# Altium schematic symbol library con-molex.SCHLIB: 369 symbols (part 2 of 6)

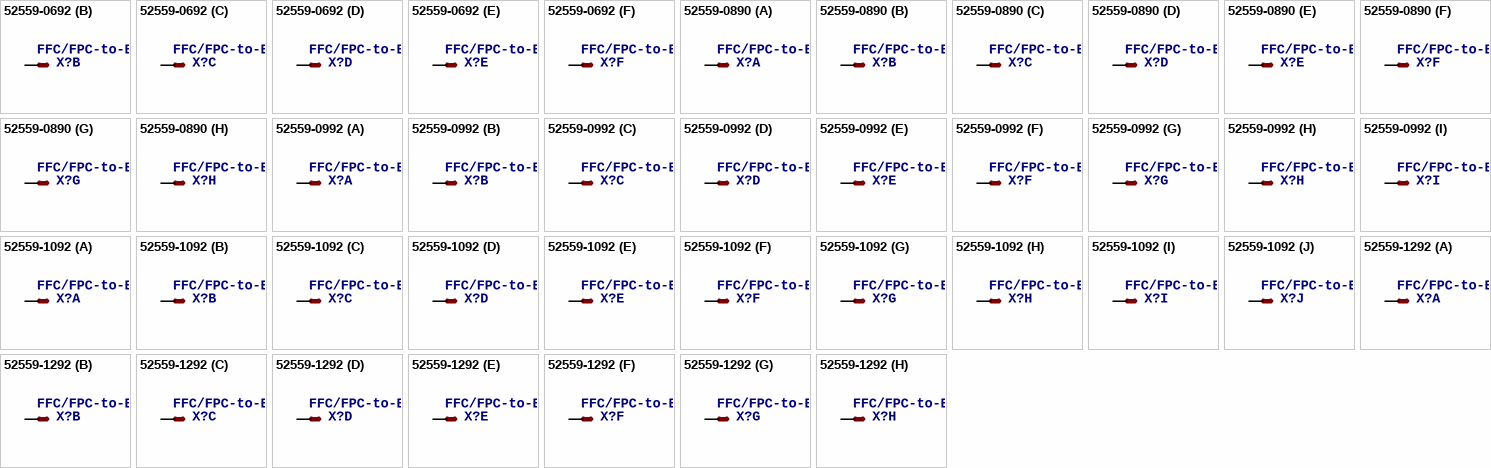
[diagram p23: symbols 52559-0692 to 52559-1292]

## 52559-0692
designator X?, comment FFC/FPC-to-Board  0.50mm (.020") SMT, Vertical, ZIF Receptacle   Source: http://www.molex.com/product/ffc/52559.html
MPN: 52559-0692
footprint 52559-0692
part A pins: 1 S
part B pins: 2 S
part C pins: 3 S
part D pins: 4 S
part E pins: 5 S
part F pins: 6 S

## 52559-0890
designator X?, comment FFC/FPC-to-Board  0.50mm (.020") SMT, Vertical, ZIF Receptacle   Source: http://www.molex.com/product/ffc/52559.html
footprint 52559-0890
part A pins: 1 S
part B pins: 2 S
part C pins: 3 S
part D pins: 4 S
part E pins: 5 S
part F pins: 6 S
part G pins: 7 S
part H pins: 8 S

## 52559-0992
designator X?, comment FFC/FPC-to-Board  0.50mm (.020") SMT, Vertical, ZIF Receptacle   Source: http://www.molex.com/product/ffc/52559.html
footprint 52559-0992
part A pins: 1 S
part B pins: 2 S
part C pins: 3 S
part D pins: 4 S
part E pins: 5 S
part F pins: 6 S
part G pins: 7 S
part H pins: 8 S
part I pins: 9 S

## 52559-1092
designator X?, comment FFC/FPC-to-Board  0.50mm (.020") SMT, Vertical, ZIF Receptacle   Source: http://www.molex.com/product/ffc/52559.html
MPN: 52559-1092
footprint 52559-1092
part A pins: 1 S
part B pins: 2 S
part C pins: 3 S
part D pins: 4 S
part E pins: 5 S
part F pins: 6 S
part G pins: 7 S
part H pins: 8 S
part I pins: 9 S
part J pins: 10 S

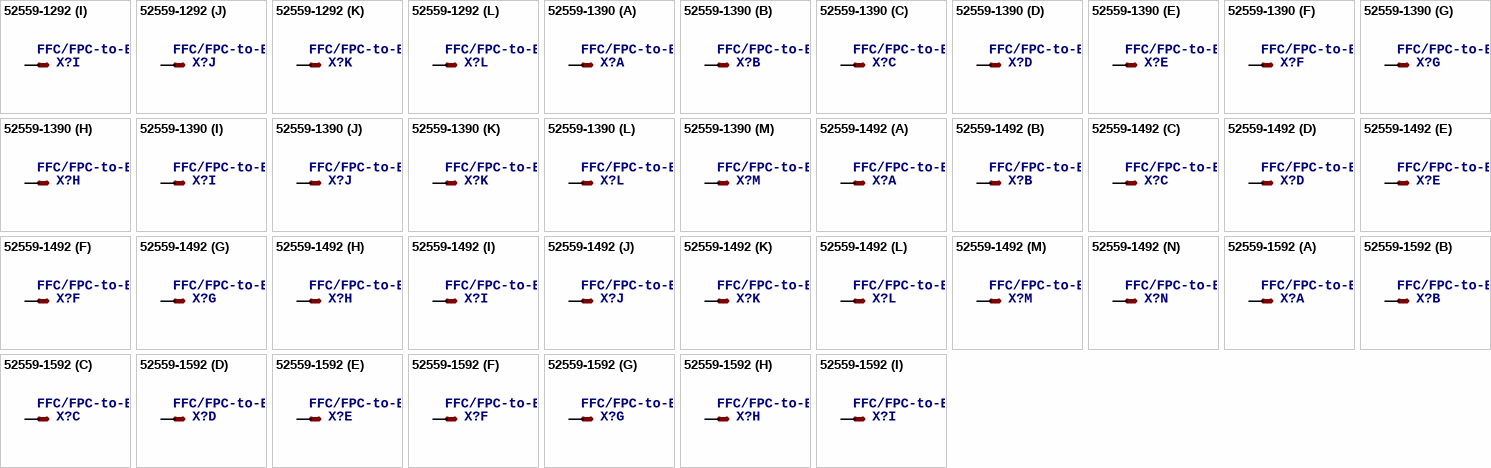
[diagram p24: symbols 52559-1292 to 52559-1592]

## 52559-1292
designator X?, comment FFC/FPC-to-Board  0.50mm (.020") SMT, Vertical, ZIF Receptacle   Source: http://www.molex.com/product/ffc/52559.html
MPN: 52559-1292
footprint 52559-1292
part A pins: 1 S
part B pins: 2 S
part C pins: 3 S
part D pins: 4 S
part E pins: 5 S
part F pins: 6 S
part G pins: 7 S
part H pins: 8 S
part I pins: 9 S
part J pins: 10 S
part K pins: 11 S
part L pins: 12 S

## 52559-1390
designator X?, comment FFC/FPC-to-Board  0.50mm (.020") SMT, Vertical, ZIF Receptacle   Source: http://www.molex.com/product/ffc/52559.html
MPN: 52559-1390
footprint 52559-1390
part A pins: 1 S
part B pins: 2 S
part C pins: 3 S
part D pins: 4 S
part E pins: 5 S
part F pins: 6 S
part G pins: 7 S
part H pins: 8 S
part I pins: 9 S
part J pins: 10 S
part K pins: 11 S
part L pins: 12 S
part M pins: 13 S

## 52559-1492
designator X?, comment FFC/FPC-to-Board  0.50mm (.020") SMT, Vertical, ZIF Receptacle   Source: http://www.molex.com/product/ffc/52559.html
MPN: 52559-1492
footprint 52559-1492
part A pins: 1 S
part B pins: 2 S
part C pins: 3 S
part D pins: 4 S
part E pins: 5 S
part F pins: 6 S
part G pins: 7 S
part H pins: 8 S
part I pins: 9 S
part J pins: 10 S
part K pins: 11 S
part L pins: 12 S
part M pins: 13 S
part N pins: 14 S

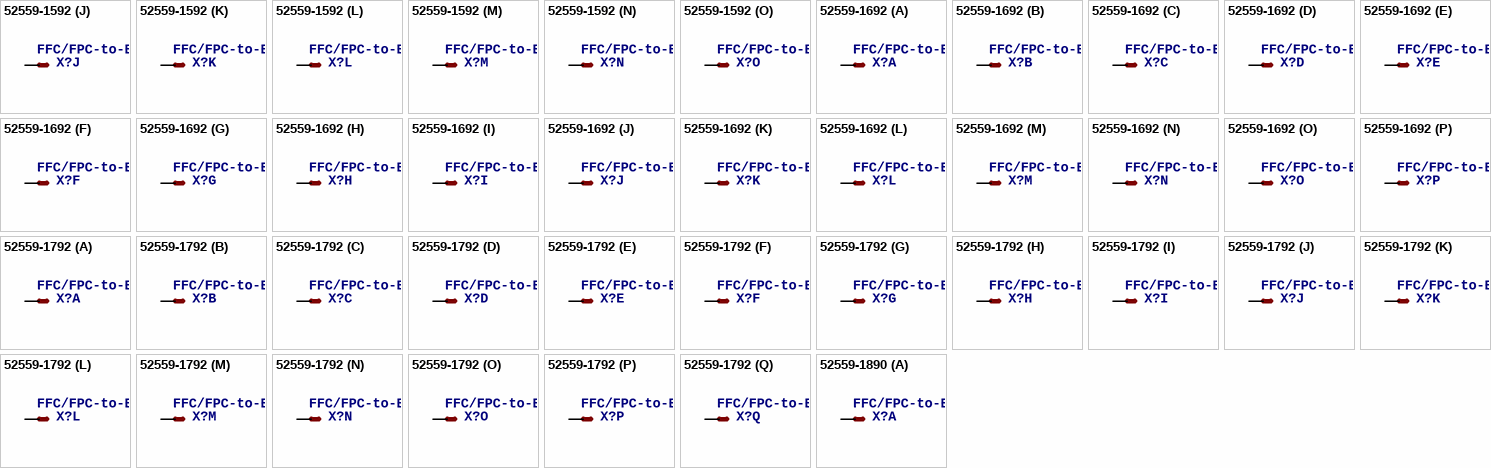
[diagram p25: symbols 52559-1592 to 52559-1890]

## 52559-1592
designator X?, comment FFC/FPC-to-Board  0.50mm (.020") SMT, Vertical, ZIF Receptacle   Source: http://www.molex.com/product/ffc/52559.html
footprint 52559-1592
part A pins: 1 S
part B pins: 2 S
part C pins: 3 S
part D pins: 4 S
part E pins: 5 S
part F pins: 6 S
part G pins: 7 S
part H pins: 8 S
part I pins: 9 S
part J pins: 10 S
part K pins: 11 S
part L pins: 12 S
part M pins: 13 S
part N pins: 14 S
part O pins: 15 S

## 52559-1692
designator X?, comment FFC/FPC-to-Board  0.50mm (.020") SMT, Vertical, ZIF Receptacle   Source: http://www.molex.com/product/ffc/52559.html
footprint 52559-1692
part A pins: 1 S
part B pins: 2 S
part C pins: 3 S
part D pins: 4 S
part E pins: 5 S
part F pins: 6 S
part G pins: 7 S
part H pins: 8 S
part I pins: 9 S
part J pins: 10 S
part K pins: 11 S
part L pins: 12 S
part M pins: 13 S
part N pins: 14 S
part O pins: 15 S
part P pins: 16 S

## 52559-1792
designator X?, comment FFC/FPC-to-Board  0.50mm (.020") SMT, Vertical, ZIF Receptacle   Source: http://www.molex.com/product/ffc/52559.html
footprint 52559-1792
part A pins: 1 S
part B pins: 2 S
part C pins: 3 S
part D pins: 4 S
part E pins: 5 S
part F pins: 6 S
part G pins: 7 S
part H pins: 8 S
part I pins: 9 S
part J pins: 10 S
part K pins: 11 S
part L pins: 12 S
part M pins: 13 S
part N pins: 14 S
part O pins: 15 S
part P pins: 16 S
part Q pins: 17 S

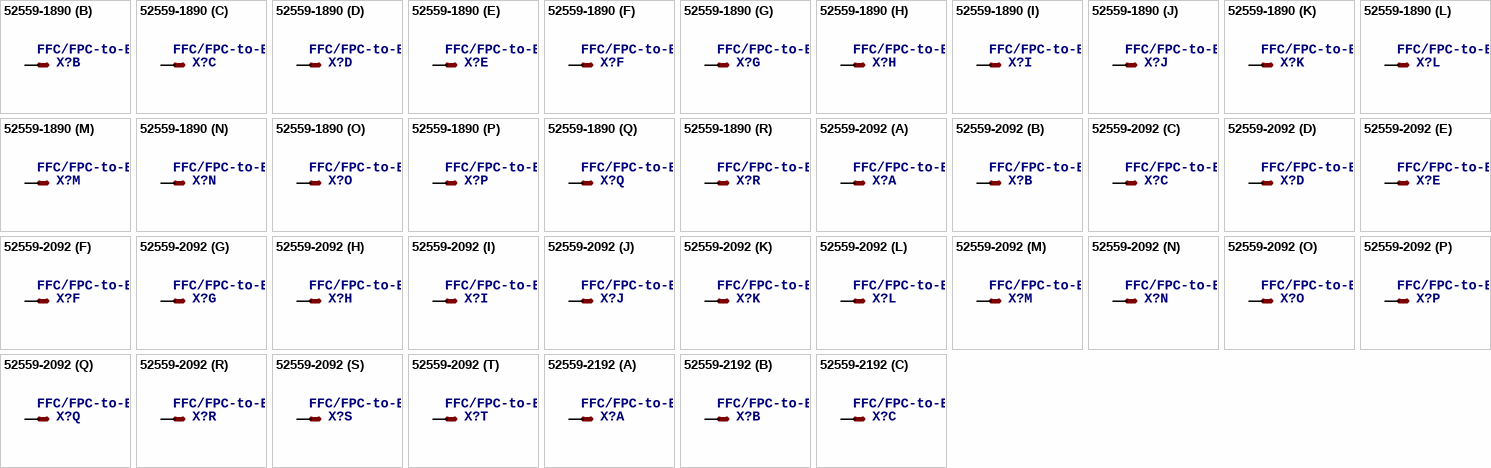
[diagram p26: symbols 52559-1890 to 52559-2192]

## 52559-1890
designator X?, comment FFC/FPC-to-Board  0.50mm (.020") SMT, Vertical, ZIF Receptacle   Source: http://www.molex.com/product/ffc/52559.html
MPN: 52559-1890
footprint 52559-1890
part A pins: 1 S
part B pins: 2 S
part C pins: 3 S
part D pins: 4 S
part E pins: 5 S
part F pins: 6 S
part G pins: 7 S
part H pins: 8 S
part I pins: 9 S
part J pins: 10 S
part K pins: 11 S
part L pins: 12 S
part M pins: 13 S
part N pins: 14 S
part O pins: 15 S
part P pins: 16 S
part Q pins: 17 S
part R pins: 18 S

## 52559-2092
designator X?, comment FFC/FPC-to-Board  0.50mm (.020") SMT, Vertical, ZIF Receptacle   Source: http://www.molex.com/product/ffc/52559.html
footprint 52559-2092
part A pins: 1 S
part B pins: 2 S
part C pins: 3 S
part D pins: 4 S
part E pins: 5 S
part F pins: 6 S
part G pins: 7 S
part H pins: 8 S
part I pins: 9 S
part J pins: 10 S
part K pins: 11 S
part L pins: 12 S
part M pins: 13 S
part N pins: 14 S
part O pins: 15 S
part P pins: 16 S
part Q pins: 17 S
part R pins: 18 S
part S pins: 19 S
part T pins: 20 S

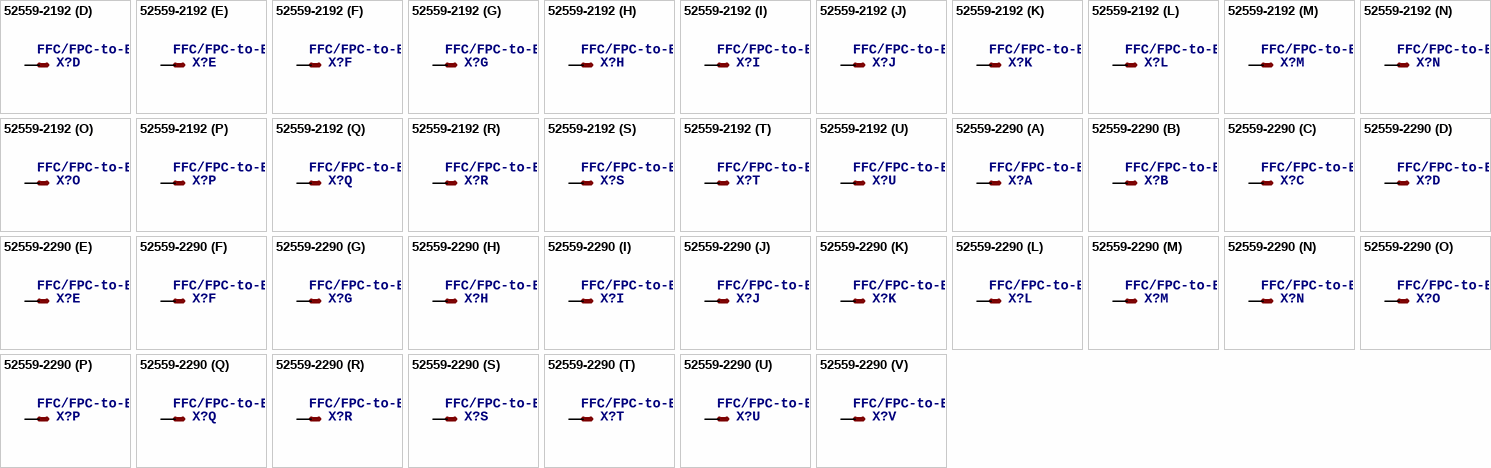
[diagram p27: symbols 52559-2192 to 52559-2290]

## 52559-2192
designator X?, comment FFC/FPC-to-Board  0.50mm (.020") SMT, Vertical, ZIF Receptacle   Source: http://www.molex.com/product/ffc/52559.html
footprint 52559-2192
part A pins: 1 S
part B pins: 2 S
part C pins: 3 S
part D pins: 4 S
part E pins: 5 S
part F pins: 6 S
part G pins: 7 S
part H pins: 8 S
part I pins: 9 S
part J pins: 10 S
part K pins: 11 S
part L pins: 12 S
part M pins: 13 S
part N pins: 14 S
part O pins: 15 S
part P pins: 16 S
part Q pins: 17 S
part R pins: 18 S
part S pins: 19 S
part T pins: 20 S
part U pins: 21 S

## 52559-2290
designator X?, comment FFC/FPC-to-Board  0.50mm (.020") SMT, Vertical, ZIF Receptacle   Source: http://www.molex.com/product/ffc/52559.html
MPN: 52559-2290
footprint 52559-2290
part A pins: 1 S
part B pins: 2 S
part C pins: 3 S
part D pins: 4 S
part E pins: 5 S
part F pins: 6 S
part G pins: 7 S
part H pins: 8 S
part I pins: 9 S
part J pins: 10 S
part K pins: 11 S
part L pins: 12 S
part M pins: 13 S
part N pins: 14 S
part O pins: 15 S
part P pins: 16 S
part Q pins: 17 S
part R pins: 18 S
part S pins: 19 S
part T pins: 20 S
part U pins: 21 S
part V pins: 22 S

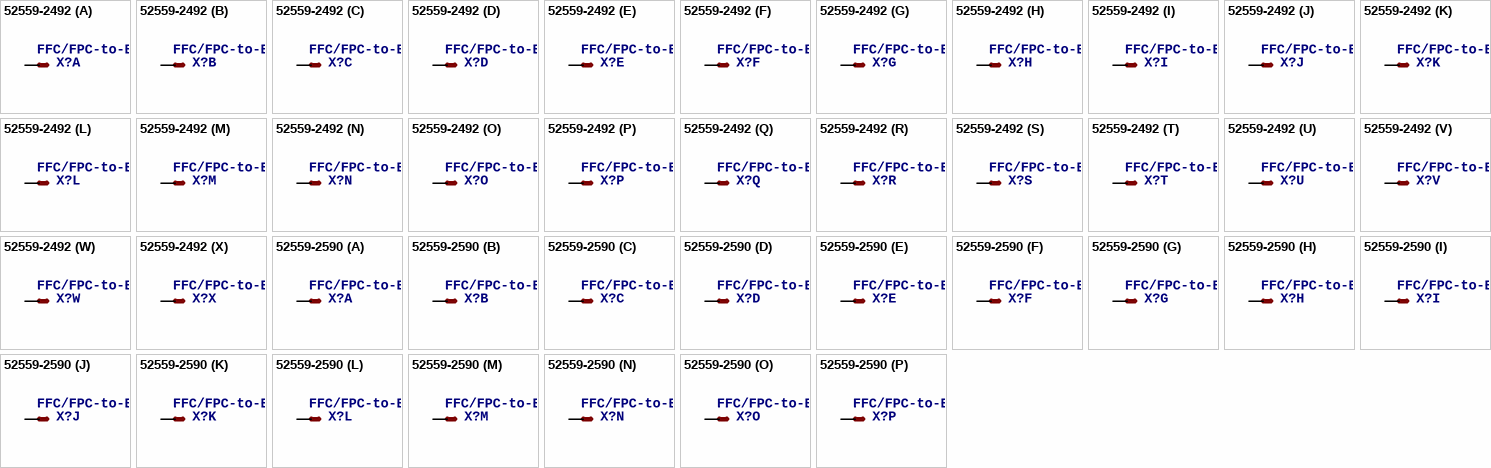
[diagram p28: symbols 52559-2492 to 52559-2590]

## 52559-2492
designator X?, comment FFC/FPC-to-Board  0.50mm (.020") SMT, Vertical, ZIF Receptacle   Source: http://www.molex.com/product/ffc/52559.html
MPN: 52559-2492
footprint 52559-2492
part A pins: 1 S
part B pins: 2 S
part C pins: 3 S
part D pins: 4 S
part E pins: 5 S
part F pins: 6 S
part G pins: 7 S
part H pins: 8 S
part I pins: 9 S
part J pins: 10 S
part K pins: 11 S
part L pins: 12 S
part M pins: 13 S
part N pins: 14 S
part O pins: 15 S
part P pins: 16 S
part Q pins: 17 S
part R pins: 18 S
part S pins: 19 S
part T pins: 20 S
part U pins: 21 S
part V pins: 22 S
part W pins: 23 S
part X pins: 24 S

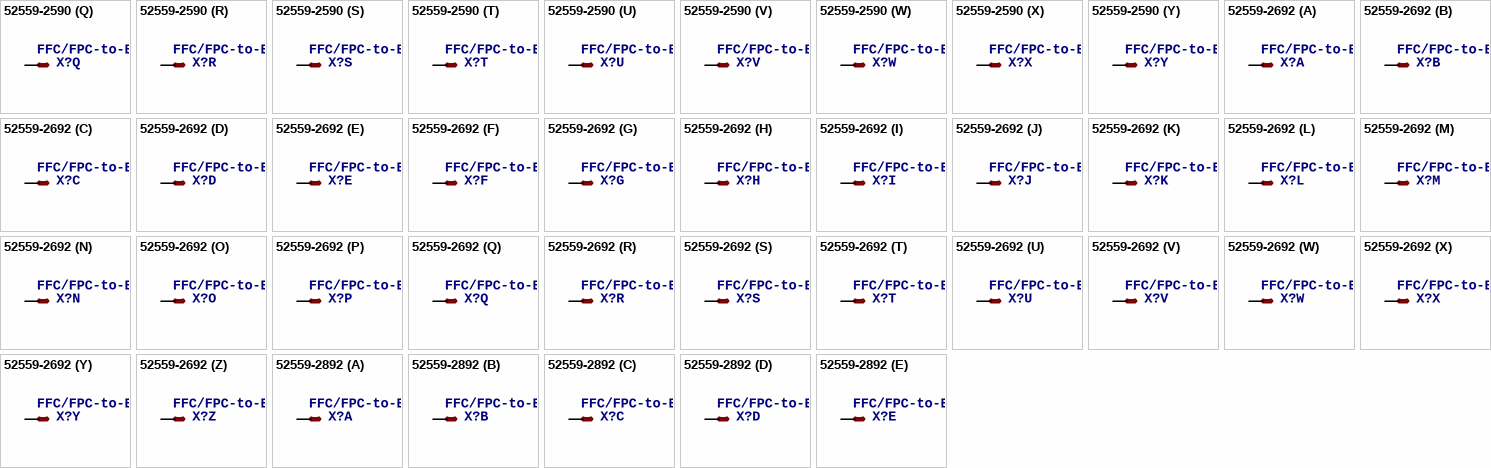
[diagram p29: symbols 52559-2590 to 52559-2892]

## 52559-2590
designator X?, comment FFC/FPC-to-Board  0.50mm (.020") SMT, Vertical, ZIF Receptacle   Source: http://www.molex.com/product/ffc/52559.html
footprint 52559-2590
part A pins: 1 S
part B pins: 2 S
part C pins: 3 S
part D pins: 4 S
part E pins: 5 S
part F pins: 6 S
part G pins: 7 S
part H pins: 8 S
part I pins: 9 S
part J pins: 10 S
part K pins: 11 S
part L pins: 12 S
part M pins: 13 S
part N pins: 14 S
part O pins: 15 S
part P pins: 16 S
part Q pins: 17 S
part R pins: 18 S
part S pins: 19 S
part T pins: 20 S
part U pins: 21 S
part V pins: 22 S
part W pins: 23 S
part X pins: 24 S
part Y pins: 25 S

## 52559-2692
designator X?, comment FFC/FPC-to-Board  0.50mm (.020") SMT, Vertical, ZIF Receptacle   Source: http://www.molex.com/product/ffc/52559.html
footprint 52559-2692
part A pins: 1 S
part B pins: 2 S
part C pins: 3 S
part D pins: 4 S
part E pins: 5 S
part F pins: 6 S
part G pins: 7 S
part H pins: 8 S
part I pins: 9 S
part J pins: 10 S
part K pins: 11 S
part L pins: 12 S
part M pins: 13 S
part N pins: 14 S
part O pins: 15 S
part P pins: 16 S
part Q pins: 17 S
part R pins: 18 S
part S pins: 19 S
part T pins: 20 S
part U pins: 21 S
part V pins: 22 S
part W pins: 23 S
part X pins: 24 S
part Y pins: 25 S
part Z pins: 26 S

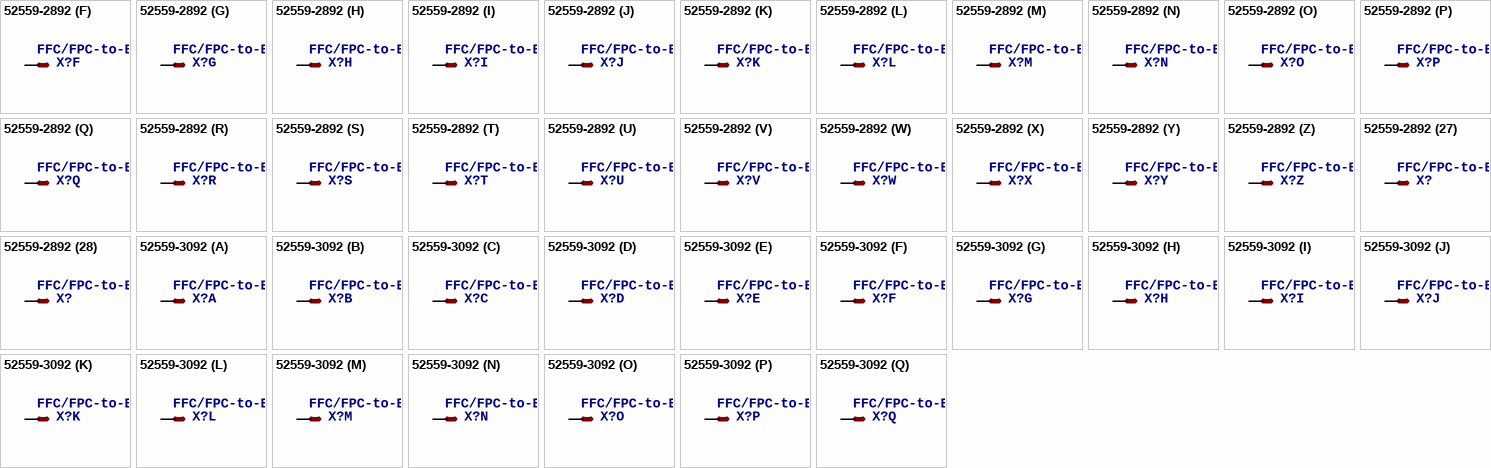
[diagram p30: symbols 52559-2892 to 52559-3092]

## 52559-2892
designator X?, comment FFC/FPC-to-Board  0.50mm (.020") SMT, Vertical, ZIF Receptacle   Source: http://www.molex.com/product/ffc/52559.html
footprint 52559-2892
part A pins: 1 S
part B pins: 2 S
part C pins: 3 S
part D pins: 4 S
part E pins: 5 S
part F pins: 6 S
part G pins: 7 S
part H pins: 8 S
part I pins: 9 S
part J pins: 10 S
part K pins: 11 S
part L pins: 12 S
part M pins: 13 S
part N pins: 14 S
part O pins: 15 S
part P pins: 16 S
part Q pins: 17 S
part R pins: 18 S
part S pins: 19 S
part T pins: 20 S
part U pins: 21 S
part V pins: 22 S
part W pins: 23 S
part X pins: 24 S
part Y pins: 25 S
part Z pins: 26 S
part 27 pins: 27 S
part 28 pins: 28 S

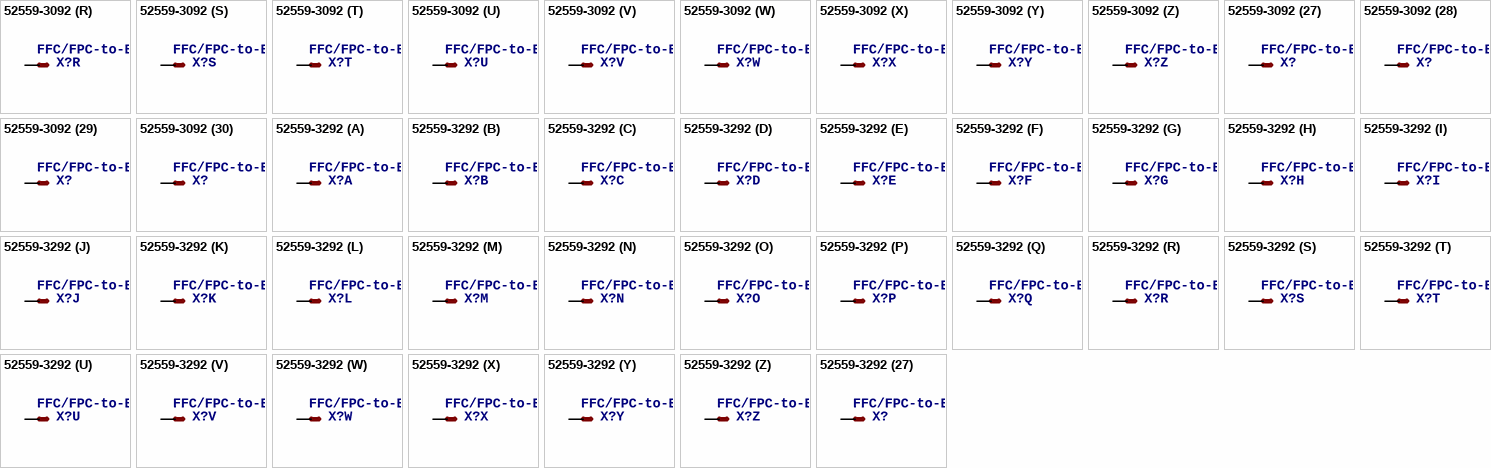
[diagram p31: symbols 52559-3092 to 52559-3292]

## 52559-3092
designator X?, comment FFC/FPC-to-Board  0.50mm (.020") SMT, Vertical, ZIF Receptacle   Source: http://www.molex.com/product/ffc/52559.html
MPN: 52559-3072; MF: MOLEX
footprint 52559-3092
part A pins: 1 S
part B pins: 2 S
part C pins: 3 S
part D pins: 4 S
part E pins: 5 S
part F pins: 6 S
part G pins: 7 S
part H pins: 8 S
part I pins: 9 S
part J pins: 10 S
part K pins: 11 S
part L pins: 12 S
part M pins: 13 S
part N pins: 14 S
part O pins: 15 S
part P pins: 16 S
part Q pins: 17 S
part R pins: 18 S
part S pins: 19 S
part T pins: 20 S
part U pins: 21 S
part V pins: 22 S
part W pins: 23 S
part X pins: 24 S
part Y pins: 25 S
part Z pins: 26 S
part 27 pins: 27 S
part 28 pins: 28 S
part 29 pins: 29 S
part 30 pins: 30 S

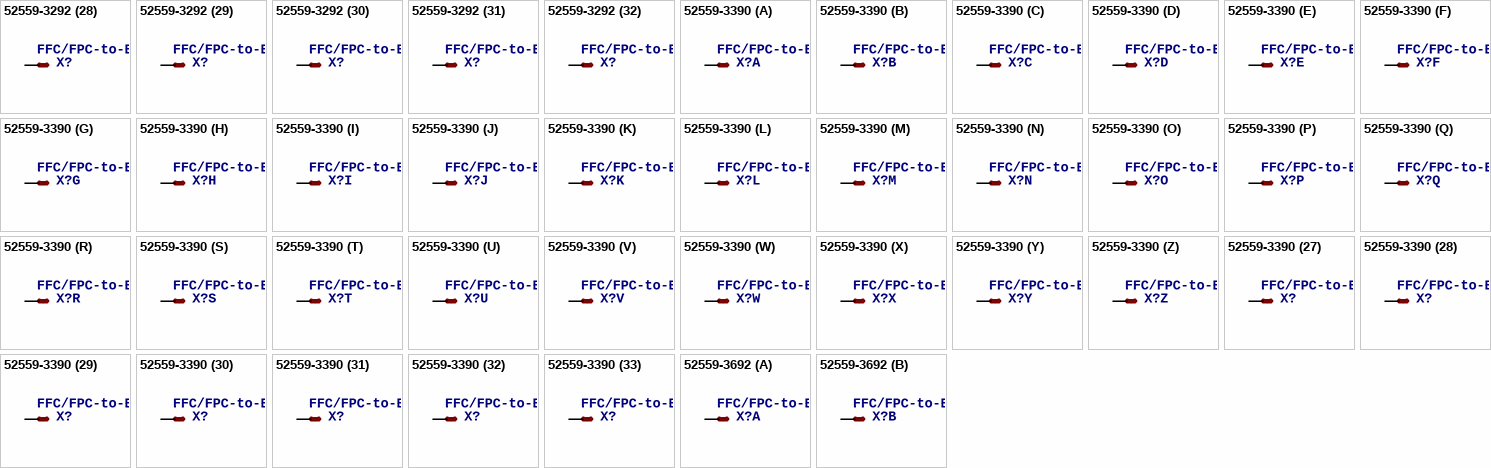
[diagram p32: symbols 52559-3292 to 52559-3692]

## 52559-3292
designator X?, comment FFC/FPC-to-Board  0.50mm (.020") SMT, Vertical, ZIF Receptacle   Source: http://www.molex.com/product/ffc/52559.html
footprint 52559-3292
part A pins: 1 S
part B pins: 2 S
part C pins: 3 S
part D pins: 4 S
part E pins: 5 S
part F pins: 6 S
part G pins: 7 S
part H pins: 8 S
part I pins: 9 S
part J pins: 10 S
part K pins: 11 S
part L pins: 12 S
part M pins: 13 S
part N pins: 14 S
part O pins: 15 S
part P pins: 16 S
part Q pins: 17 S
part R pins: 18 S
part S pins: 19 S
part T pins: 20 S
part U pins: 21 S
part V pins: 22 S
part W pins: 23 S
part X pins: 24 S
part Y pins: 25 S
part Z pins: 26 S
part 27 pins: 27 S
part 28 pins: 28 S
part 29 pins: 29 S
part 30 pins: 30 S
part 31 pins: 31 S
part 32 pins: 32 S

## 52559-3390
designator X?, comment FFC/FPC-to-Board  0.50mm (.020") SMT, Vertical, ZIF Receptacle   Source: http://www.molex.com/product/ffc/52559.html
footprint 52559-3390
part A pins: 1 S
part B pins: 2 S
part C pins: 3 S
part D pins: 4 S
part E pins: 5 S
part F pins: 6 S
part G pins: 7 S
part H pins: 8 S
part I pins: 9 S
part J pins: 10 S
part K pins: 11 S
part L pins: 12 S
part M pins: 13 S
part N pins: 14 S
part O pins: 15 S
part P pins: 16 S
part Q pins: 17 S
part R pins: 18 S
part S pins: 19 S
part T pins: 20 S
part U pins: 21 S
part V pins: 22 S
part W pins: 23 S
part X pins: 24 S
part Y pins: 25 S
part Z pins: 26 S
part 27 pins: 27 S
part 28 pins: 28 S
part 29 pins: 29 S
part 30 pins: 30 S
part 31 pins: 31 S
part 32 pins: 32 S
part 33 pins: 33 S

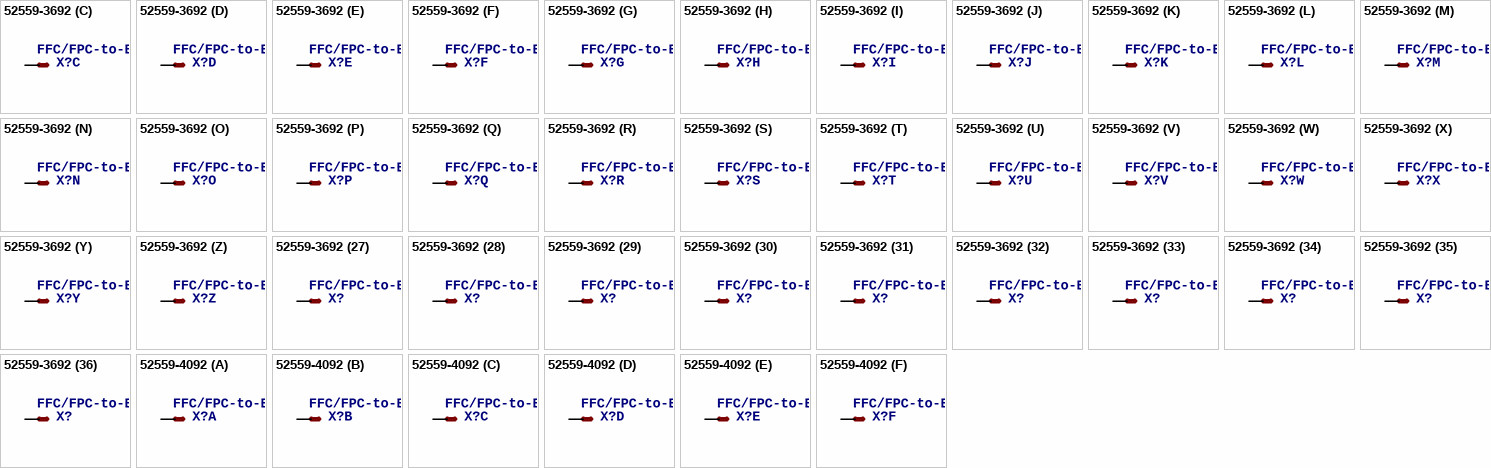
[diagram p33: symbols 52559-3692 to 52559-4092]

## 52559-3692
designator X?, comment FFC/FPC-to-Board  0.50mm (.020") SMT, Vertical, ZIF Receptacle   Source: http://www.molex.com/product/ffc/52559.html
footprint 52559-3692
part A pins: 1 S
part B pins: 2 S
part C pins: 3 S
part D pins: 4 S
part E pins: 5 S
part F pins: 6 S
part G pins: 7 S
part H pins: 8 S
part I pins: 9 S
part J pins: 10 S
part K pins: 11 S
part L pins: 12 S
part M pins: 13 S
part N pins: 14 S
part O pins: 15 S
part P pins: 16 S
part Q pins: 17 S
part R pins: 18 S
part S pins: 19 S
part T pins: 20 S
part U pins: 21 S
part V pins: 22 S
part W pins: 23 S
part X pins: 24 S
part Y pins: 25 S
part Z pins: 26 S
part 27 pins: 27 S
part 28 pins: 28 S
part 29 pins: 29 S
part 30 pins: 30 S
part 31 pins: 31 S
part 32 pins: 32 S
part 33 pins: 33 S
part 34 pins: 34 S
part 35 pins: 35 S
part 36 pins: 36 S

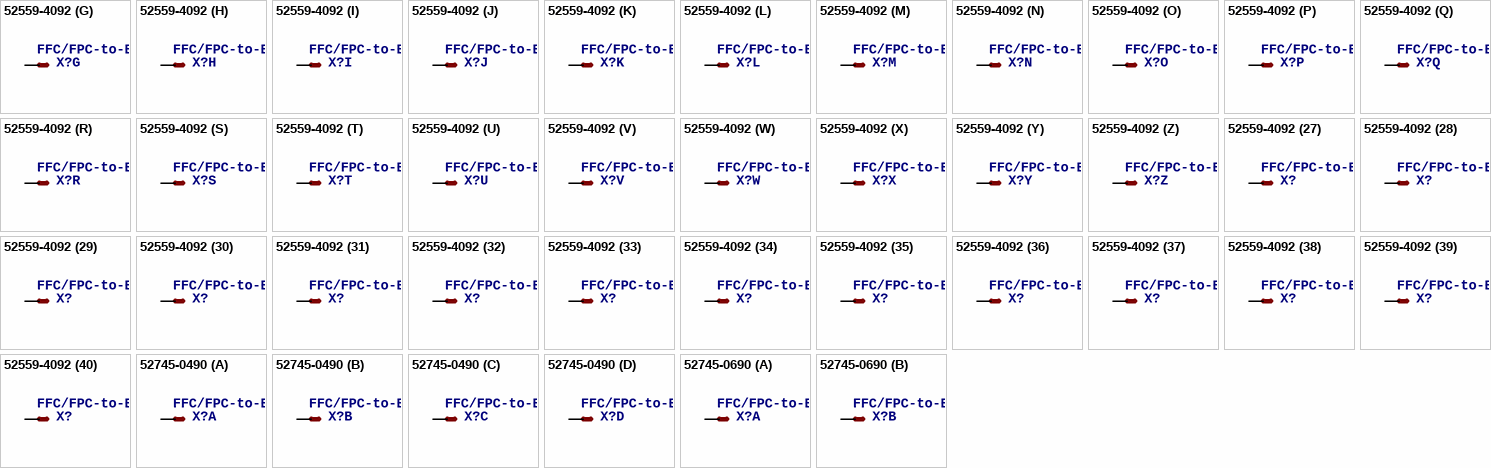
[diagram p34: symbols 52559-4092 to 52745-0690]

## 52559-4092
designator X?, comment FFC/FPC-to-Board  0.50mm (.020") SMT, Vertical, ZIF Receptacle   Source: http://www.molex.com/product/ffc/52559.html
MPN: 52559-4092
footprint 52559-4092
part A pins: 1 S
part B pins: 2 S
part C pins: 3 S
part D pins: 4 S
part E pins: 5 S
part F pins: 6 S
part G pins: 7 S
part H pins: 8 S
part I pins: 9 S
part J pins: 10 S
part K pins: 11 S
part L pins: 12 S
part M pins: 13 S
part N pins: 14 S
part O pins: 15 S
part P pins: 16 S
part Q pins: 17 S
part R pins: 18 S
part S pins: 19 S
part T pins: 20 S
part U pins: 21 S
part V pins: 22 S
part W pins: 23 S
part X pins: 24 S
part Y pins: 25 S
part Z pins: 26 S
part 27 pins: 27 S
part 28 pins: 28 S
part 29 pins: 29 S
part 30 pins: 30 S
part 31 pins: 31 S
part 32 pins: 32 S
part 33 pins: 33 S
part 34 pins: 34 S
part 35 pins: 35 S
part 36 pins: 36 S
part 37 pins: 37 S
part 38 pins: 38 S
part 39 pins: 39 S
part 40 pins: 40 S

## 52745-0490
designator X?, comment FFC/FPC-to-Board  0.50mm (.020") SMT Top Contact   Right Angle, ZIF, Style Receptacle 52745 / 52435 Source: http://www.molex.com/product/ffc/52745.html
MPN: 52745-0490
footprint 52745-0490
part A pins: 1 S
part B pins: 2 S
part C pins: 3 S
part D pins: 4 S

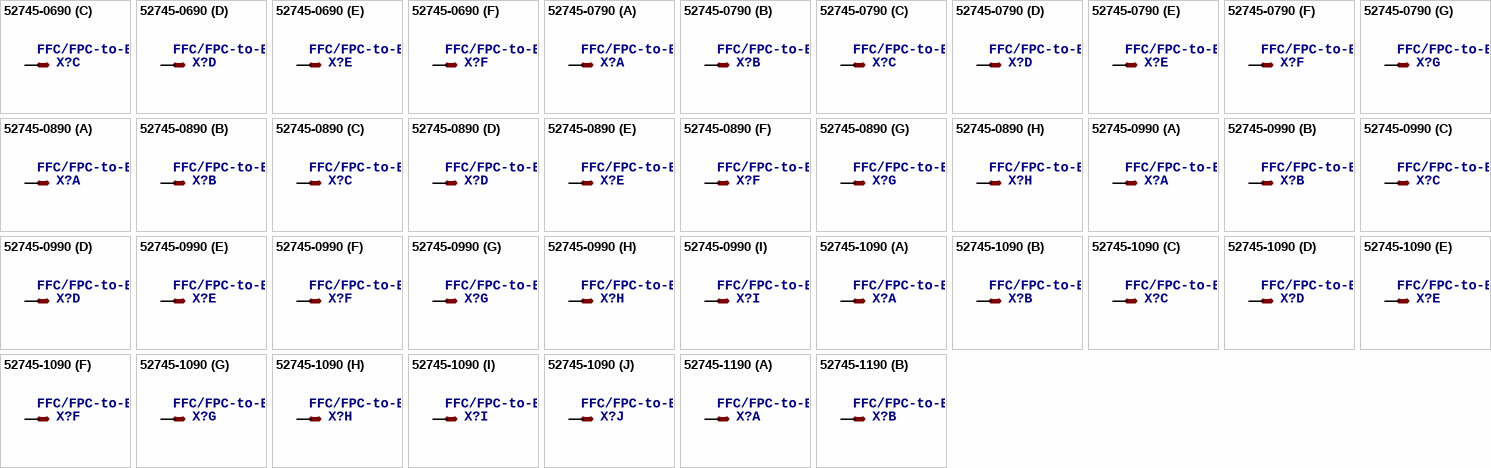
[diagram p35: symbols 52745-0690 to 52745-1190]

## 52745-0690
designator X?, comment FFC/FPC-to-Board  0.50mm (.020") SMT Top Contact   Right Angle, ZIF, Style Receptacle 52745 / 52435 Source: http://www.molex.com/product/ffc/52745.html
MPN: 52745-0690
footprint 52745-0690
part A pins: 1 S
part B pins: 2 S
part C pins: 3 S
part D pins: 4 S
part E pins: 5 S
part F pins: 6 S

## 52745-0790
designator X?, comment FFC/FPC-to-Board  0.50mm (.020") SMT Top Contact   Right Angle, ZIF, Style Receptacle 52745 / 52435 Source: http://www.molex.com/product/ffc/52745.html
footprint 52745-0790
part A pins: 1 S
part B pins: 2 S
part C pins: 3 S
part D pins: 4 S
part E pins: 5 S
part F pins: 6 S
part G pins: 7 S

## 52745-0890
designator X?, comment FFC/FPC-to-Board  0.50mm (.020") SMT Top Contact   Right Angle, ZIF, Style Receptacle 52745 / 52435 Source: http://www.molex.com/product/ffc/52745.html
MPN: 52745-0890
footprint 52745-0890
part A pins: 1 S
part B pins: 2 S
part C pins: 3 S
part D pins: 4 S
part E pins: 5 S
part F pins: 6 S
part G pins: 7 S
part H pins: 8 S

## 52745-0990
designator X?, comment FFC/FPC-to-Board  0.50mm (.020") SMT Top Contact   Right Angle, ZIF, Style Receptacle 52745 / 52435 Source: http://www.molex.com/product/ffc/52745.html
footprint 52745-0990
part A pins: 1 S
part B pins: 2 S
part C pins: 3 S
part D pins: 4 S
part E pins: 5 S
part F pins: 6 S
part G pins: 7 S
part H pins: 8 S
part I pins: 9 S

## 52745-1090
designator X?, comment FFC/FPC-to-Board  0.50mm (.020") SMT Top Contact   Right Angle, ZIF, Style Receptacle 52745 / 52435 Source: http://www.molex.com/product/ffc/52745.html
MPN: 52745-1090
footprint 52745-1090
part A pins: 1 S
part B pins: 2 S
part C pins: 3 S
part D pins: 4 S
part E pins: 5 S
part F pins: 6 S
part G pins: 7 S
part H pins: 8 S
part I pins: 9 S
part J pins: 10 S

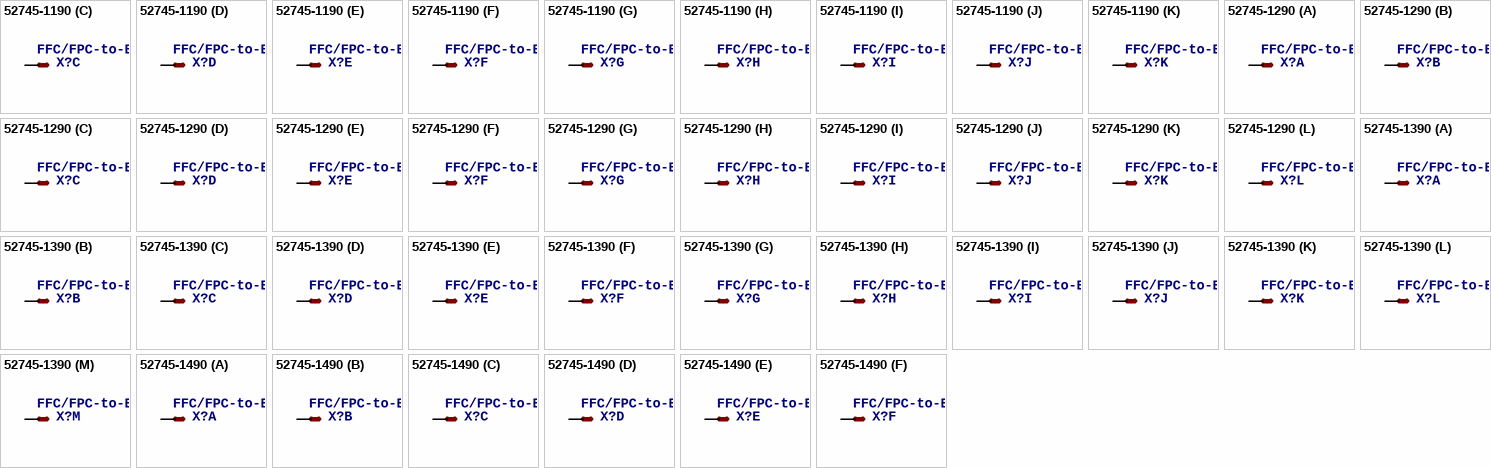
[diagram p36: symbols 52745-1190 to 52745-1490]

## 52745-1190
designator X?, comment FFC/FPC-to-Board  0.50mm (.020") SMT Top Contact   Right Angle, ZIF, Style Receptacle 52745 / 52435 Source: http://www.molex.com/product/ffc/52745.html
footprint 52745-1190
part A pins: 1 S
part B pins: 2 S
part C pins: 3 S
part D pins: 4 S
part E pins: 5 S
part F pins: 6 S
part G pins: 7 S
part H pins: 8 S
part I pins: 9 S
part J pins: 10 S
part K pins: 11 S

## 52745-1290
designator X?, comment FFC/FPC-to-Board  0.50mm (.020") SMT Top Contact   Right Angle, ZIF, Style Receptacle 52745 / 52435 Source: http://www.molex.com/product/ffc/52745.html
MPN: 52745-1290
footprint 52745-1290
part A pins: 1 S
part B pins: 2 S
part C pins: 3 S
part D pins: 4 S
part E pins: 5 S
part F pins: 6 S
part G pins: 7 S
part H pins: 8 S
part I pins: 9 S
part J pins: 10 S
part K pins: 11 S
part L pins: 12 S

## 52745-1390
designator X?, comment FFC/FPC-to-Board  0.50mm (.020") SMT Top Contact   Right Angle, ZIF, Style Receptacle 52745 / 52435 Source: http://www.molex.com/product/ffc/52745.html
footprint 52745-1390
part A pins: 1 S
part B pins: 2 S
part C pins: 3 S
part D pins: 4 S
part E pins: 5 S
part F pins: 6 S
part G pins: 7 S
part H pins: 8 S
part I pins: 9 S
part J pins: 10 S
part K pins: 11 S
part L pins: 12 S
part M pins: 13 S

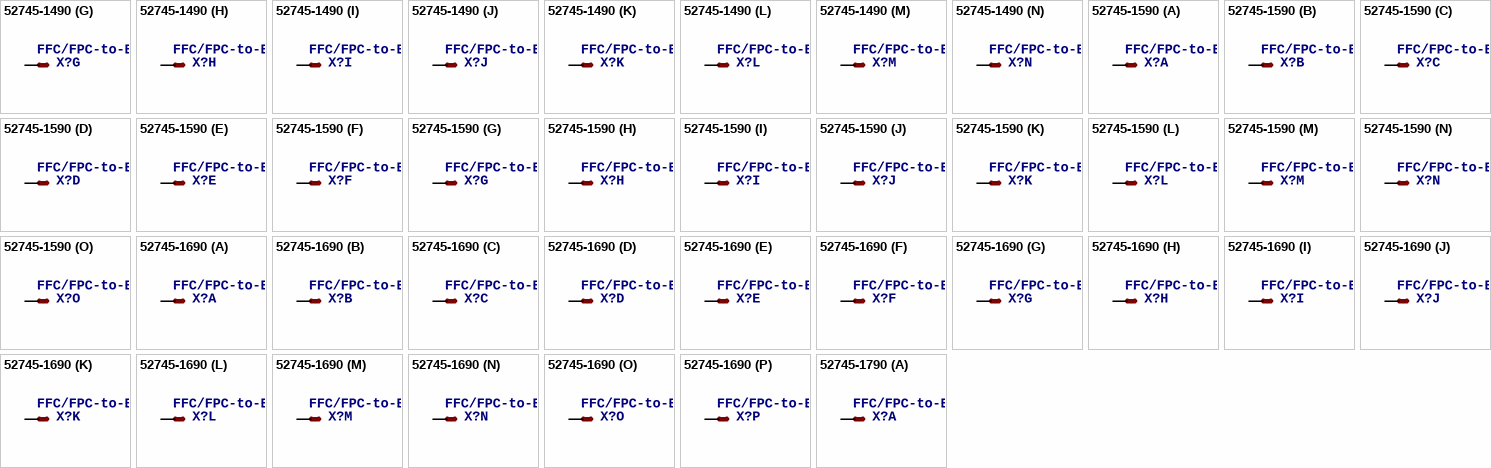
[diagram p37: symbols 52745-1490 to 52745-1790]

## 52745-1490
designator X?, comment FFC/FPC-to-Board  0.50mm (.020") SMT Top Contact   Right Angle, ZIF, Style Receptacle 52745 / 52435 Source: http://www.molex.com/product/ffc/52745.html
MPN: 52745-1490; MF: WALDOM/MOLEX
footprint 52745-1490
part A pins: 1 S
part B pins: 2 S
part C pins: 3 S
part D pins: 4 S
part E pins: 5 S
part F pins: 6 S
part G pins: 7 S
part H pins: 8 S
part I pins: 9 S
part J pins: 10 S
part K pins: 11 S
part L pins: 12 S
part M pins: 13 S
part N pins: 14 S

## 52745-1590
designator X?, comment FFC/FPC-to-Board  0.50mm (.020") SMT Top Contact   Right Angle, ZIF, Style Receptacle 52745 / 52435 Source: http://www.molex.com/product/ffc/52745.html
MPN: 52745-1590
footprint 52745-1590
part A pins: 1 S
part B pins: 2 S
part C pins: 3 S
part D pins: 4 S
part E pins: 5 S
part F pins: 6 S
part G pins: 7 S
part H pins: 8 S
part I pins: 9 S
part J pins: 10 S
part K pins: 11 S
part L pins: 12 S
part M pins: 13 S
part N pins: 14 S
part O pins: 15 S

## 52745-1690
designator X?, comment FFC/FPC-to-Board  0.50mm (.020") SMT Top Contact   Right Angle, ZIF, Style Receptacle 52745 / 52435 Source: http://www.molex.com/product/ffc/52745.html
MPN: 52745-1690; MF: MOLEX
footprint 52745-1690
part A pins: 1 S
part B pins: 2 S
part C pins: 3 S
part D pins: 4 S
part E pins: 5 S
part F pins: 6 S
part G pins: 7 S
part H pins: 8 S
part I pins: 9 S
part J pins: 10 S
part K pins: 11 S
part L pins: 12 S
part M pins: 13 S
part N pins: 14 S
part O pins: 15 S
part P pins: 16 S

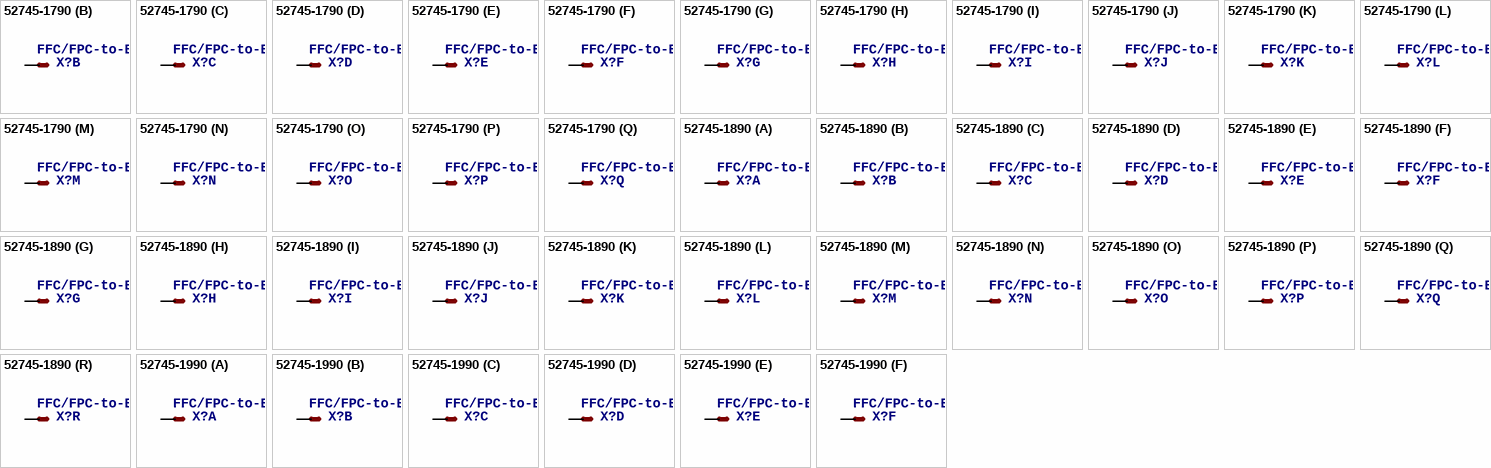
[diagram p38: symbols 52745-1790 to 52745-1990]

## 52745-1790
designator X?, comment FFC/FPC-to-Board  0.50mm (.020") SMT Top Contact   Right Angle, ZIF, Style Receptacle 52745 / 52435 Source: http://www.molex.com/product/ffc/52745.html
MPN: 52745-1790
footprint 52745-1790
part A pins: 1 S
part B pins: 2 S
part C pins: 3 S
part D pins: 4 S
part E pins: 5 S
part F pins: 6 S
part G pins: 7 S
part H pins: 8 S
part I pins: 9 S
part J pins: 10 S
part K pins: 11 S
part L pins: 12 S
part M pins: 13 S
part N pins: 14 S
part O pins: 15 S
part P pins: 16 S
part Q pins: 17 S

## 52745-1890
designator X?, comment FFC/FPC-to-Board  0.50mm (.020") SMT Top Contact   Right Angle, ZIF, Style Receptacle 52745 / 52435 Source: http://www.molex.com/product/ffc/52745.html
MPN: 52745-1890
footprint 52745-1890
part A pins: 1 S
part B pins: 2 S
part C pins: 3 S
part D pins: 4 S
part E pins: 5 S
part F pins: 6 S
part G pins: 7 S
part H pins: 8 S
part I pins: 9 S
part J pins: 10 S
part K pins: 11 S
part L pins: 12 S
part M pins: 13 S
part N pins: 14 S
part O pins: 15 S
part P pins: 16 S
part Q pins: 17 S
part R pins: 18 S

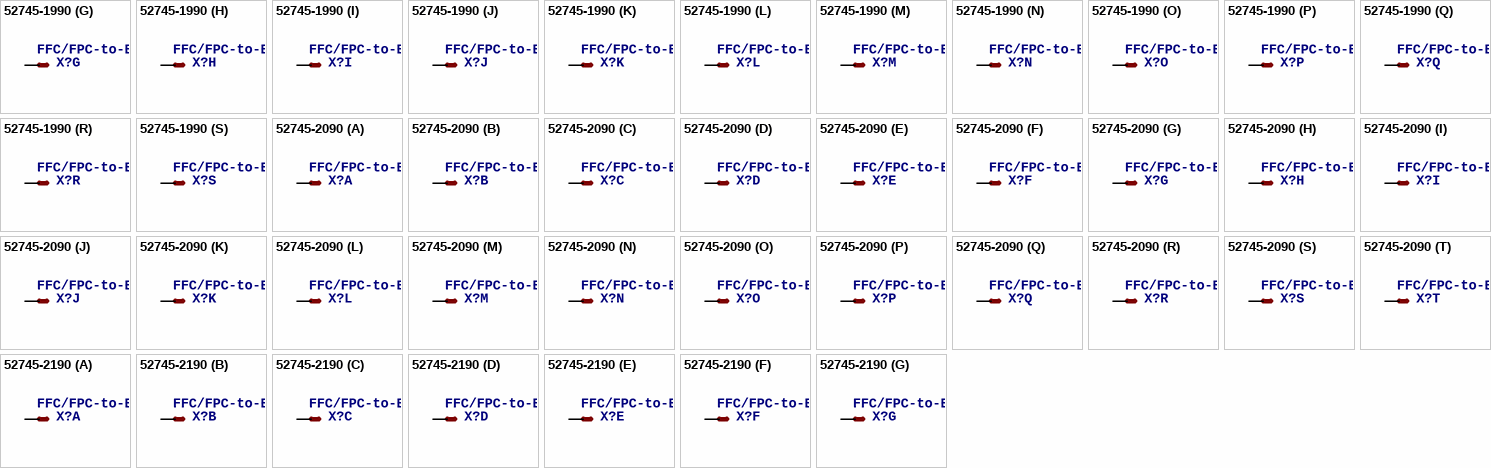
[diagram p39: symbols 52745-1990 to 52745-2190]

## 52745-1990
designator X?, comment FFC/FPC-to-Board  0.50mm (.020") SMT Top Contact   Right Angle, ZIF, Style Receptacle 52745 / 52435 Source: http://www.molex.com/product/ffc/52745.html
MPN: 52745-1990
footprint 52745-1990
part A pins: 1 S
part B pins: 2 S
part C pins: 3 S
part D pins: 4 S
part E pins: 5 S
part F pins: 6 S
part G pins: 7 S
part H pins: 8 S
part I pins: 9 S
part J pins: 10 S
part K pins: 11 S
part L pins: 12 S
part M pins: 13 S
part N pins: 14 S
part O pins: 15 S
part P pins: 16 S
part Q pins: 17 S
part R pins: 18 S
part S pins: 19 S

## 52745-2090
designator X?, comment FFC/FPC-to-Board  0.50mm (.020") SMT Top Contact   Right Angle, ZIF, Style Receptacle 52745 / 52435 Source: http://www.molex.com/product/ffc/52745.html
MPN: 52745-2090; MF: WALDOM/MOLEX
footprint 52745-2090
part A pins: 1 S
part B pins: 2 S
part C pins: 3 S
part D pins: 4 S
part E pins: 5 S
part F pins: 6 S
part G pins: 7 S
part H pins: 8 S
part I pins: 9 S
part J pins: 10 S
part K pins: 11 S
part L pins: 12 S
part M pins: 13 S
part N pins: 14 S
part O pins: 15 S
part P pins: 16 S
part Q pins: 17 S
part R pins: 18 S
part S pins: 19 S
part T pins: 20 S

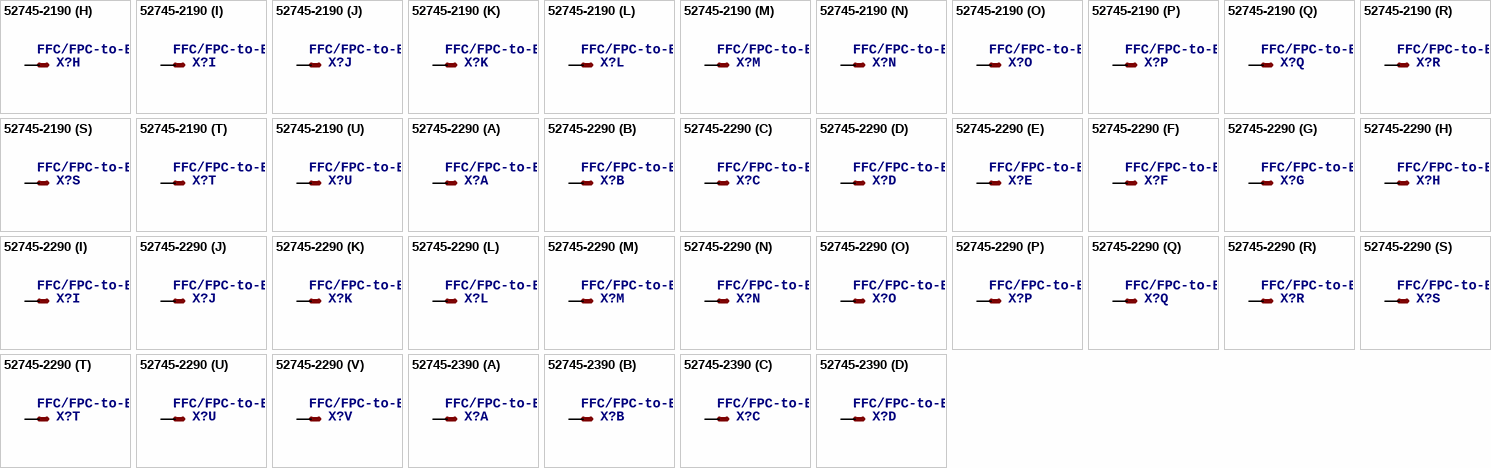
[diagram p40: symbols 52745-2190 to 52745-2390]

## 52745-2190
designator X?, comment FFC/FPC-to-Board  0.50mm (.020") SMT Top Contact   Right Angle, ZIF, Style Receptacle 52745 / 52435 Source: http://www.molex.com/product/ffc/52745.html
footprint 52745-2190
part A pins: 1 S
part B pins: 2 S
part C pins: 3 S
part D pins: 4 S
part E pins: 5 S
part F pins: 6 S
part G pins: 7 S
part H pins: 8 S
part I pins: 9 S
part J pins: 10 S
part K pins: 11 S
part L pins: 12 S
part M pins: 13 S
part N pins: 14 S
part O pins: 15 S
part P pins: 16 S
part Q pins: 17 S
part R pins: 18 S
part S pins: 19 S
part T pins: 20 S
part U pins: 21 S

## 52745-2290
designator X?, comment FFC/FPC-to-Board  0.50mm (.020") SMT Top Contact   Right Angle, ZIF, Style Receptacle 52745 / 52435 Source: http://www.molex.com/product/ffc/52745.html
footprint 52745-2290
part A pins: 1 S
part B pins: 2 S
part C pins: 3 S
part D pins: 4 S
part E pins: 5 S
part F pins: 6 S
part G pins: 7 S
part H pins: 8 S
part I pins: 9 S
part J pins: 10 S
part K pins: 11 S
part L pins: 12 S
part M pins: 13 S
part N pins: 14 S
part O pins: 15 S
part P pins: 16 S
part Q pins: 17 S
part R pins: 18 S
part S pins: 19 S
part T pins: 20 S
part U pins: 21 S
part V pins: 22 S

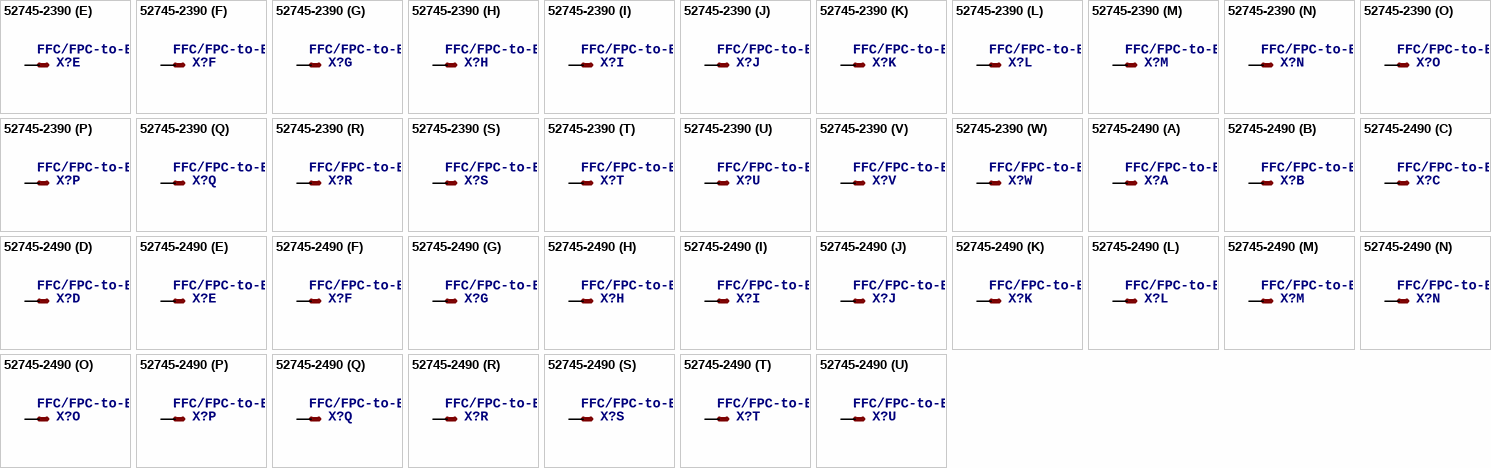
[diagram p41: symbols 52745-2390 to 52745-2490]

## 52745-2390
designator X?, comment FFC/FPC-to-Board  0.50mm (.020") SMT Top Contact   Right Angle, ZIF, Style Receptacle 52745 / 52435 Source: http://www.molex.com/product/ffc/52745.html
footprint 52745-2390
part A pins: 1 S
part B pins: 2 S
part C pins: 3 S
part D pins: 4 S
part E pins: 5 S
part F pins: 6 S
part G pins: 7 S
part H pins: 8 S
part I pins: 9 S
part J pins: 10 S
part K pins: 11 S
part L pins: 12 S
part M pins: 13 S
part N pins: 14 S
part O pins: 15 S
part P pins: 16 S
part Q pins: 17 S
part R pins: 18 S
part S pins: 19 S
part T pins: 20 S
part U pins: 21 S
part V pins: 22 S
part W pins: 23 S

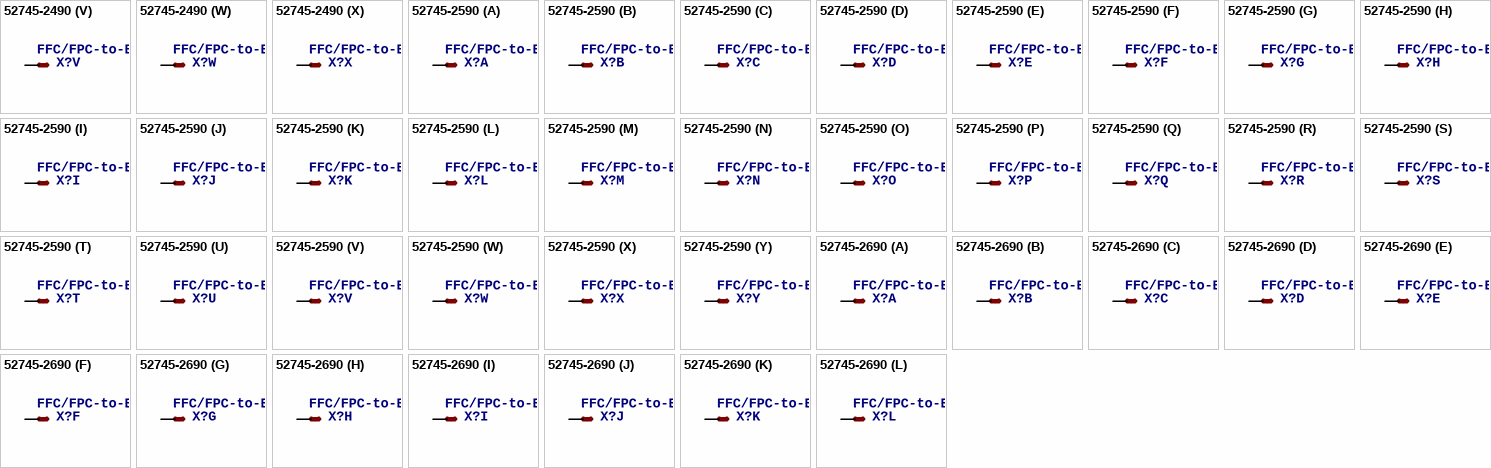
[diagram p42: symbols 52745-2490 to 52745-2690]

## 52745-2490
designator X?, comment FFC/FPC-to-Board  0.50mm (.020") SMT Top Contact   Right Angle, ZIF, Style Receptacle 52745 / 52435 Source: http://www.molex.com/product/ffc/52745.html
footprint 52745-2490
part A pins: 1 S
part B pins: 2 S
part C pins: 3 S
part D pins: 4 S
part E pins: 5 S
part F pins: 6 S
part G pins: 7 S
part H pins: 8 S
part I pins: 9 S
part J pins: 10 S
part K pins: 11 S
part L pins: 12 S
part M pins: 13 S
part N pins: 14 S
part O pins: 15 S
part P pins: 16 S
part Q pins: 17 S
part R pins: 18 S
part S pins: 19 S
part T pins: 20 S
part U pins: 21 S
part V pins: 22 S
part W pins: 23 S
part X pins: 24 S

## 52745-2590
designator X?, comment FFC/FPC-to-Board  0.50mm (.020") SMT Top Contact   Right Angle, ZIF, Style Receptacle 52745 / 52435 Source: http://www.molex.com/product/ffc/52745.html
footprint 52745-2590
part A pins: 1 S
part B pins: 2 S
part C pins: 3 S
part D pins: 4 S
part E pins: 5 S
part F pins: 6 S
part G pins: 7 S
part H pins: 8 S
part I pins: 9 S
part J pins: 10 S
part K pins: 11 S
part L pins: 12 S
part M pins: 13 S
part N pins: 14 S
part O pins: 15 S
part P pins: 16 S
part Q pins: 17 S
part R pins: 18 S
part S pins: 19 S
part T pins: 20 S
part U pins: 21 S
part V pins: 22 S
part W pins: 23 S
part X pins: 24 S
part Y pins: 25 S

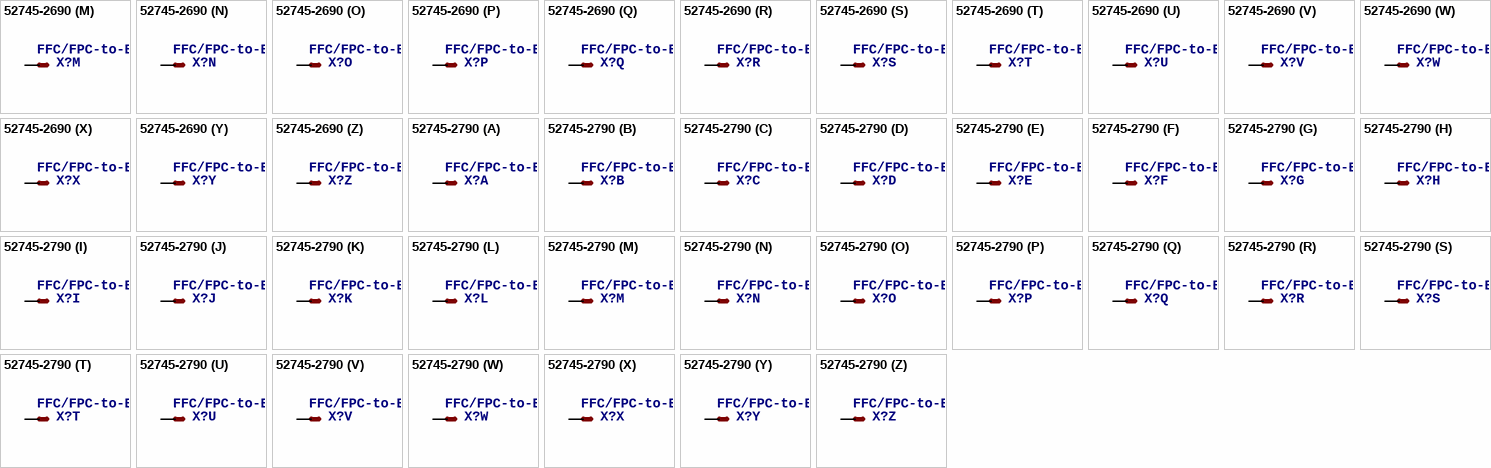
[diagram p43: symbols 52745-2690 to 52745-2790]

## 52745-2690
designator X?, comment FFC/FPC-to-Board  0.50mm (.020") SMT Top Contact   Right Angle, ZIF, Style Receptacle 52745 / 52435 Source: http://www.molex.com/product/ffc/52745.html
footprint 52745-2690
part A pins: 1 S
part B pins: 2 S
part C pins: 3 S
part D pins: 4 S
part E pins: 5 S
part F pins: 6 S
part G pins: 7 S
part H pins: 8 S
part I pins: 9 S
part J pins: 10 S
part K pins: 11 S
part L pins: 12 S
part M pins: 13 S
part N pins: 14 S
part O pins: 15 S
part P pins: 16 S
part Q pins: 17 S
part R pins: 18 S
part S pins: 19 S
part T pins: 20 S
part U pins: 21 S
part V pins: 22 S
part W pins: 23 S
part X pins: 24 S
part Y pins: 25 S
part Z pins: 26 S

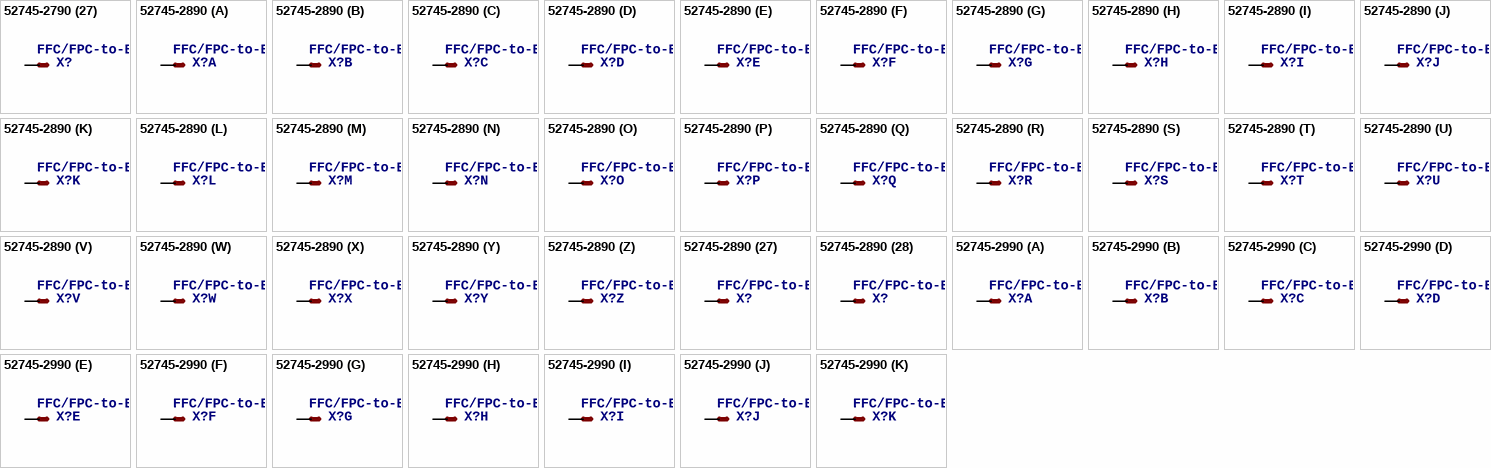
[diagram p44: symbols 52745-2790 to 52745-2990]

## 52745-2790
designator X?, comment FFC/FPC-to-Board  0.50mm (.020") SMT Top Contact   Right Angle, ZIF, Style Receptacle 52745 / 52435 Source: http://www.molex.com/product/ffc/52745.html
footprint 52745-2790
part A pins: 1 S
part B pins: 2 S
part C pins: 3 S
part D pins: 4 S
part E pins: 5 S
part F pins: 6 S
part G pins: 7 S
part H pins: 8 S
part I pins: 9 S
part J pins: 10 S
part K pins: 11 S
part L pins: 12 S
part M pins: 13 S
part N pins: 14 S
part O pins: 15 S
part P pins: 16 S
part Q pins: 17 S
part R pins: 18 S
part S pins: 19 S
part T pins: 20 S
part U pins: 21 S
part V pins: 22 S
part W pins: 23 S
part X pins: 24 S
part Y pins: 25 S
part Z pins: 26 S
part 27 pins: 27 S

## 52745-2890
designator X?, comment FFC/FPC-to-Board  0.50mm (.020") SMT Top Contact   Right Angle, ZIF, Style Receptacle 52745 / 52435 Source: http://www.molex.com/product/ffc/52745.html
footprint 52745-2890
part A pins: 1 S
part B pins: 2 S
part C pins: 3 S
part D pins: 4 S
part E pins: 5 S
part F pins: 6 S
part G pins: 7 S
part H pins: 8 S
part I pins: 9 S
part J pins: 10 S
part K pins: 11 S
part L pins: 12 S
part M pins: 13 S
part N pins: 14 S
part O pins: 15 S
part P pins: 16 S
part Q pins: 17 S
part R pins: 18 S
part S pins: 19 S
part T pins: 20 S
part U pins: 21 S
part V pins: 22 S
part W pins: 23 S
part X pins: 24 S
part Y pins: 25 S
part Z pins: 26 S
part 27 pins: 27 S
part 28 pins: 28 S

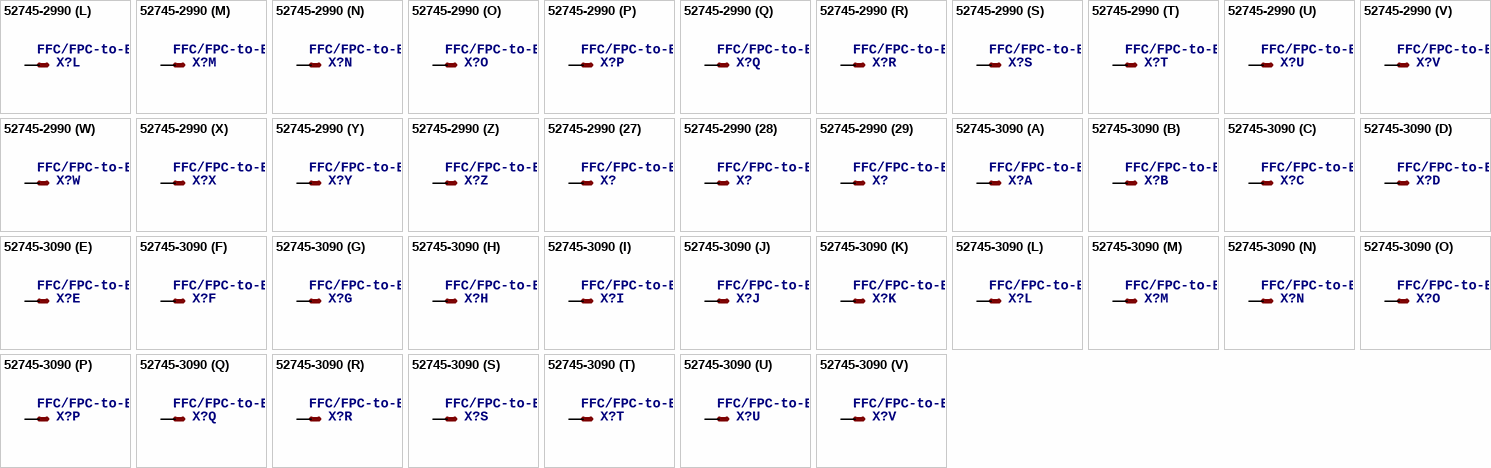
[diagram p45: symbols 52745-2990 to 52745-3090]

## 52745-2990
designator X?, comment FFC/FPC-to-Board  0.50mm (.020") SMT Top Contact   Right Angle, ZIF, Style Receptacle 52745 / 52435 Source: http://www.molex.com/product/ffc/52745.html
footprint 52745-2990
part A pins: 1 S
part B pins: 2 S
part C pins: 3 S
part D pins: 4 S
part E pins: 5 S
part F pins: 6 S
part G pins: 7 S
part H pins: 8 S
part I pins: 9 S
part J pins: 10 S
part K pins: 11 S
part L pins: 12 S
part M pins: 13 S
part N pins: 14 S
part O pins: 15 S
part P pins: 16 S
part Q pins: 17 S
part R pins: 18 S
part S pins: 19 S
part T pins: 20 S
part U pins: 21 S
part V pins: 22 S
part W pins: 23 S
part X pins: 24 S
part Y pins: 25 S
part Z pins: 26 S
part 27 pins: 27 S
part 28 pins: 28 S
part 29 pins: 29 S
